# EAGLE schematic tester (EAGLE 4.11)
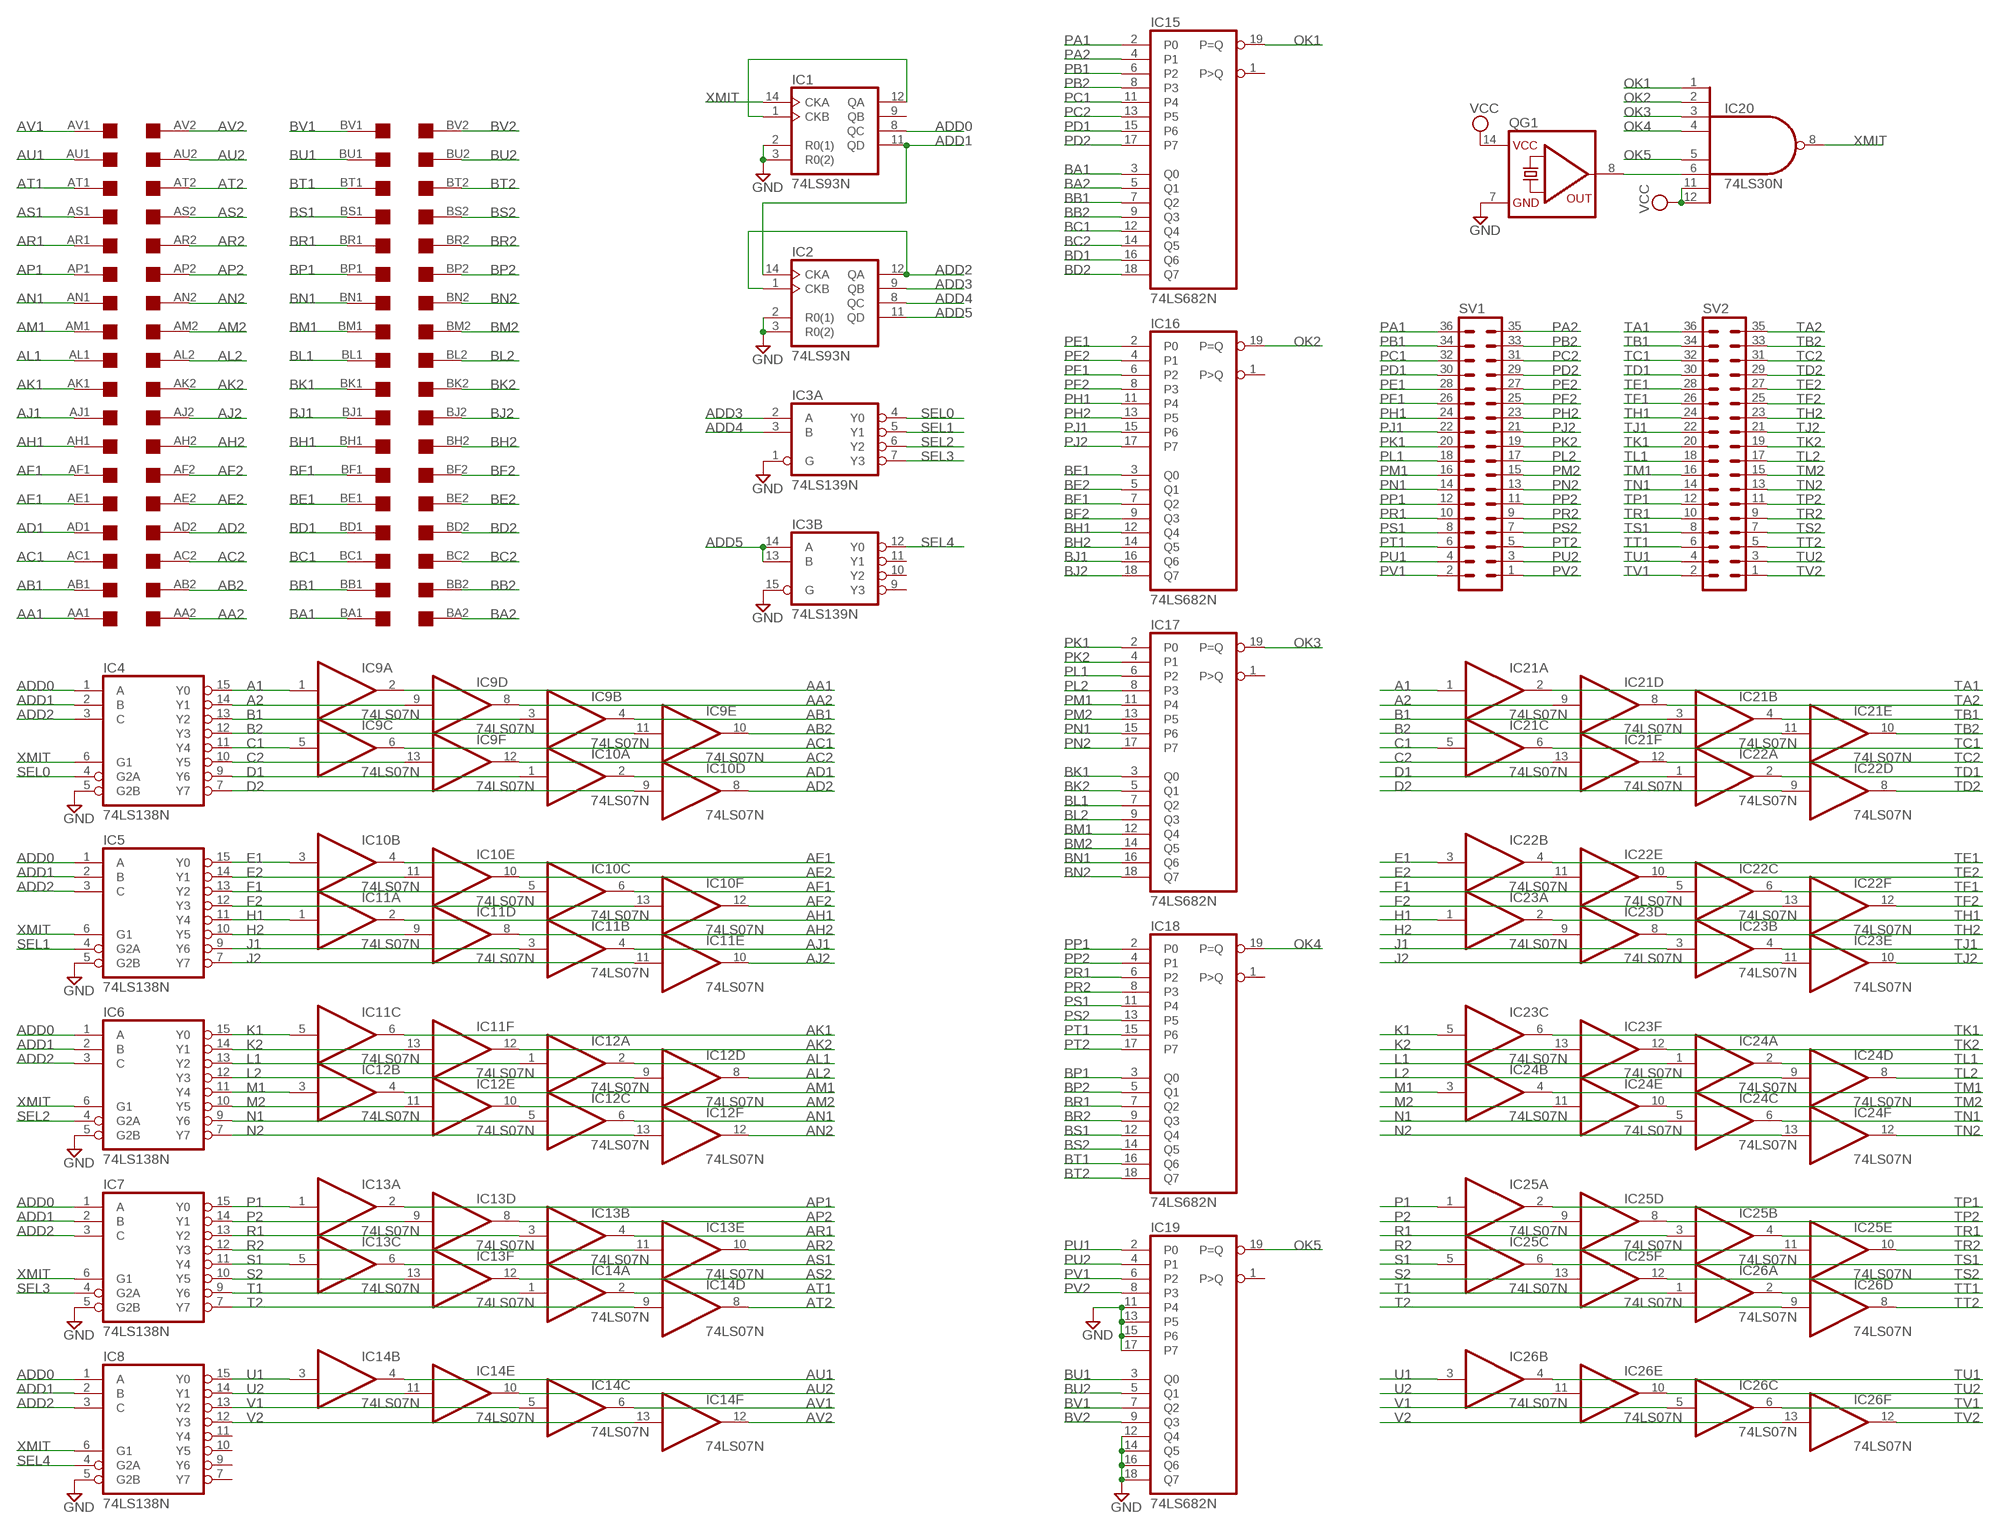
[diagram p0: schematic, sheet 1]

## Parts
IC1  74LS93N  [DIL14]
IC2  74LS93N  [DIL14]
IC3  74LS139N  [DIL16]
IC4  74LS138N  [DIL16]
IC5  74LS138N  [DIL16]
IC6  74LS138N  [DIL16]
IC7  74LS138N  [DIL16]
IC8  74LS138N  [DIL16]
IC9  74LS07N  [DIL14]
IC10  74LS07N  [DIL14]
IC11  74LS07N  [DIL14]
IC12  74LS07N  [DIL14]
IC13  74LS07N  [DIL14]
IC14  74LS07N  [DIL14]
IC15  74LS682N  [DIL20]
IC16  74LS682N  [DIL20]
IC17  74LS682N  [DIL20]
IC18  74LS682N  [DIL20]
IC19  74LS682N  [DIL20]
IC20  74LS30N  [DIL14]
IC21  74LS07N  [DIL14]
IC22  74LS07N  [DIL14]
IC23  74LS07N  [DIL14]
IC24  74LS07N  [DIL14]
IC25  74LS07N  [DIL14]
IC26  74LS07N  [DIL14]
QG1  QG5860  [DIL14S]
SV1  MA18-2  [MA18-2]
SV2  MA18-2  [MA18-2]
U$1  DOUBLEBOARD  [DOUBLE]

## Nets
A1: IC4.15(Y0) IC9.1(A:I) IC21.1(A:I)
A2: IC4.14(Y1) IC9.9(D:I) IC21.9(D:I)
AA1: IC9.2(A:O) U$1.AA1
AA2: IC9.8(D:O) U$1.AA2
AB1: IC9.4(B:O) U$1.AB1
AB2: IC9.10(E:O) U$1.AB2
AC1: IC9.6(C:O) U$1.AC1
AC2: IC9.12(F:O) U$1.AC2
AD1: IC10.2(A:O) U$1.AD1
AD2: IC10.8(D:O) U$1.AD2
ADD0: IC1.8(QC) IC4.1(A) IC5.1(A) IC6.1(A) IC7.1(A) IC8.1(A)
ADD1: IC1.11(QD) IC2.14(CKA) IC4.2(B) IC5.2(B) IC6.2(B) IC7.2(B) IC8.2(B)
ADD2: IC2.1(CKB) IC2.12(QA) IC4.3(C) IC5.3(C) IC6.3(C) IC7.3(C) IC8.3(C)
ADD3: IC2.9(QB) IC3.2(A:A)
ADD4: IC2.8(QC) IC3.3(A:B)
ADD5: IC2.11(QD) IC3.13(B:B) IC3.14(B:A)
AE1: IC10.4(B:O) U$1.AE1
AE2: IC10.10(E:O) U$1.AE2
AF1: IC10.6(C:O) U$1.AF1
AF2: IC10.12(F:O) U$1.AF2
AH1: IC11.2(A:O) U$1.AH1
AH2: IC11.8(D:O) U$1.AH2
AJ1: IC11.4(B:O) U$1.AJ1
AJ2: IC11.10(E:O) U$1.AJ2
AK1: IC11.6(C:O) U$1.AK1
AK2: IC11.12(F:O) U$1.AK2
AL1: IC12.2(A:O) U$1.AL1
AL2: IC12.8(D:O) U$1.AL2
AM1: IC12.4(B:O) U$1.AM1
AM2: IC12.10(E:O) U$1.AM2
AN1: IC12.6(C:O) U$1.AN1
AN2: IC12.12(F:O) U$1.AN2
AP1: IC13.2(A:O) U$1.AP1
AP2: IC13.8(D:O) U$1.AP2
AR1: IC13.4(B:O) U$1.AR1
AR2: IC13.10(E:O) U$1.AR2
AS1: IC13.6(C:O) U$1.AS1
AS2: IC13.12(F:O) U$1.AS2
AT1: IC14.2(A:O) U$1.AT1
AT2: IC14.8(D:O) U$1.AT2
AU1: IC14.4(B:O) U$1.AU1
AU2: IC14.10(E:O) U$1.AU2
AV1: IC14.6(C:O) U$1.AV1
AV2: IC14.12(F:O) U$1.AV2
B1: IC4.13(Y2) IC9.3(B:I) IC21.3(B:I)
B2: IC4.12(Y3) IC9.11(E:I) IC21.11(E:I)
BA1: IC15.3(Q0) U$1.BA1
BA2: IC15.5(Q1) U$1.BA2
BB1: IC15.7(Q2) U$1.BB1
BB2: IC15.9(Q3) U$1.BB2
BC1: IC15.12(Q4) U$1.BC1
BC2: IC15.14(Q5) U$1.BC2
BD1: IC15.16(Q6) U$1.BD1
BD2: IC15.18(Q7) U$1.BD2
BE1: IC16.3(Q0) U$1.BE1
BE2: IC16.5(Q1) U$1.BE2
BF1: IC16.7(Q2) U$1.BF1
BF2: IC16.9(Q3) U$1.BF2
BH1: IC16.12(Q4) U$1.BH1
BH2: IC16.14(Q5) U$1.BH2
BJ1: IC16.16(Q6) U$1.BJ1
BJ2: IC16.18(Q7) U$1.BJ2
BK1: IC17.3(Q0) U$1.BK1
BK2: IC17.5(Q1) U$1.BK2
BL1: IC17.7(Q2) U$1.BL1
BL2: IC17.9(Q3) U$1.BL2
BM1: IC17.12(Q4) U$1.BM1
BM2: IC17.14(Q5) U$1.BM2
BN1: IC17.16(Q6) U$1.BN1
BN2: IC17.18(Q7) U$1.BN2
BP1: IC18.3(Q0) U$1.BP1
BP2: IC18.5(Q1) U$1.BP2
BR1: IC18.7(Q2) U$1.BR1
BR2: IC18.9(Q3) U$1.BR2
BS1: IC18.12(Q4) U$1.BS1
BS2: IC18.14(Q5) U$1.BS2
BT1: IC18.16(Q6) U$1.BT1
BT2: IC18.18(Q7) U$1.BT2
BU1: IC19.3(Q0) U$1.BU1
BU2: IC19.5(Q1) U$1.BU2
BV1: IC19.7(Q2) U$1.BV1
BV2: IC19.9(Q3) U$1.BV2
C1: IC4.11(Y4) IC9.5(C:I) IC21.5(C:I)
C2: IC4.10(Y5) IC9.13(F:I) IC21.13(F:I)
CLK1: IC1.1(CKB) IC1.12(QA)
D1: IC4.9(Y6) IC10.1(A:I) IC22.1(A:I)
D2: IC4.7(Y7) IC10.9(D:I) IC22.9(D:I)
E1: IC5.15(Y0) IC10.3(B:I) IC22.3(B:I)
E2: IC5.14(Y1) IC10.11(E:I) IC22.11(E:I)
F1: IC5.13(Y2) IC10.5(C:I) IC22.5(C:I)
F2: IC5.12(Y3) IC10.13(F:I) IC22.13(F:I)
GND: IC1.2(R0(1)) IC1.3(R0(2)) IC2.2(R0(1)) IC2.3(R0(2)) IC3.1(A:G) IC3.15(B:G) IC4.5(G2B) IC5.5(G2B) IC6.5(G2B) IC7.5(G2B) IC8.5(G2B) IC19.11(P4) IC19.12(Q4) IC19.13(P5) IC19.14(Q5) IC19.15(P6) IC19.16(Q6) IC19.17(P7) IC19.18(Q7) QG1.7(GND)
H1: IC5.11(Y4) IC11.1(A:I) IC23.1(A:I)
H2: IC5.10(Y5) IC11.9(D:I) IC23.9(D:I)
J1: IC5.9(Y6) IC11.3(B:I) IC23.3(B:I)
J2: IC5.7(Y7) IC11.11(E:I) IC23.11(E:I)
K1: IC6.15(Y0) IC11.5(C:I) IC23.5(C:I)
K2: IC6.14(Y1) IC11.13(F:I) IC23.13(F:I)
L1: IC6.13(Y2) IC12.1(A:I) IC24.1(A:I)
L2: IC6.12(Y3) IC12.9(D:I) IC24.9(D:I)
M1: IC6.11(Y4) IC12.3(B:I) IC24.3(B:I)
M2: IC6.10(Y5) IC12.11(E:I) IC24.11(E:I)
N1: IC6.9(Y6) IC12.5(C:I) IC24.5(C:I)
N2: IC6.7(Y7) IC12.13(F:I) IC24.13(F:I)
N$1: IC20.6(I5) QG1.8(OUT)
OK1: IC15.19(P=Q) IC20.1(I0)
OK2: IC16.19(P=Q) IC20.2(I1)
OK3: IC17.19(P=Q) IC20.3(I2)
OK4: IC18.19(P=Q) IC20.4(I3)
OK5: IC19.19(P=Q) IC20.5(I4)
P1: IC7.15(Y0) IC13.1(A:I) IC25.1(A:I)
P2: IC7.14(Y1) IC13.9(D:I) IC25.9(D:I)
PA1: IC15.2(P0) SV1.36
PA2: IC15.4(P1) SV1.35
PB1: IC15.6(P2) SV1.34
PB2: IC15.8(P3) SV1.33
PC1: IC15.11(P4) SV1.32
PC2: IC15.13(P5) SV1.31
PD1: IC15.15(P6) SV1.30
PD2: IC15.17(P7) SV1.29
PE1: IC16.2(P0) SV1.28
PE2: IC16.4(P1) SV1.27
PF1: IC16.6(P2) SV1.26
PF2: IC16.8(P3) SV1.25
PH1: IC16.11(P4) SV1.24
PH2: IC16.13(P5) SV1.23
PJ1: IC16.15(P6) SV1.22
PJ2: IC16.17(P7) SV1.21
PK1: IC17.2(P0) SV1.20
PK2: IC17.4(P1) SV1.19
PL1: IC17.6(P2) SV1.18
PL2: IC17.8(P3) SV1.17
PM1: IC17.11(P4) SV1.16
PM2: IC17.13(P5) SV1.15
PN1: IC17.15(P6) SV1.14
PN2: IC17.17(P7) SV1.13
PP1: IC18.2(P0) SV1.12
PP2: IC18.4(P1) SV1.11
PR1: IC18.6(P2) SV1.10
PR2: IC18.8(P3) SV1.9
PS1: IC18.11(P4) SV1.8
PS2: IC18.13(P5) SV1.7
PT1: IC18.15(P6) SV1.6
PT2: IC18.17(P7) SV1.5
PU1: IC19.2(P0) SV1.4
PU2: IC19.4(P1) SV1.3
PV1: IC19.6(P2) SV1.2
PV2: IC19.8(P3) SV1.1
R1: IC7.13(Y2) IC13.3(B:I) IC25.3(B:I)
R2: IC7.12(Y3) IC13.11(E:I) IC25.11(E:I)
S1: IC7.11(Y4) IC13.5(C:I) IC25.5(C:I)
S2: IC7.10(Y5) IC13.13(F:I) IC25.13(F:I)
SEL0: IC3.4(A:Y0) IC4.4(G2A)
SEL1: IC3.5(A:Y1) IC5.4(G2A)
SEL2: IC3.6(A:Y2) IC6.4(G2A)
SEL3: IC3.7(A:Y3) IC7.4(G2A)
SEL4: IC3.12(B:Y0) IC8.4(G2A)
T1: IC7.9(Y6) IC14.1(A:I) IC26.1(A:I)
T2: IC7.7(Y7) IC14.9(D:I) IC26.9(D:I)
TA1: IC21.2(A:O) SV2.36
TA2: IC21.8(D:O) SV2.35
TB1: IC21.4(B:O) SV2.34
TB2: IC21.10(E:O) SV2.33
TC1: IC21.6(C:O) SV2.32
TC2: IC21.12(F:O) SV2.31
TD1: IC22.2(A:O) SV2.30
TD2: IC22.8(D:O) SV2.29
TE1: IC22.4(B:O) SV2.28
TE2: IC22.10(E:O) SV2.27
TF1: IC22.6(C:O) SV2.26
TF2: IC22.12(F:O) SV2.25
TH1: IC23.2(A:O) SV2.24
TH2: IC23.8(D:O) SV2.23
TJ1: IC23.4(B:O) SV2.22
TJ2: IC23.10(E:O) SV2.21
TK1: IC23.6(C:O) SV2.20
TK2: IC23.12(F:O) SV2.19
TL1: IC24.2(A:O) SV2.18
TL2: IC24.8(D:O) SV2.17
TM1: IC24.4(B:O) SV2.16
TM2: IC24.10(E:O) SV2.15
TN1: IC24.6(C:O) SV2.14
TN2: IC24.12(F:O) SV2.13
TP1: IC25.2(A:O) SV2.12
TP2: IC25.8(D:O) SV2.11
TR1: IC25.4(B:O) SV2.10
TR2: IC25.10(E:O) SV2.9
TS1: IC25.6(C:O) SV2.8
TS2: IC25.12(F:O) SV2.7
TT1: IC26.2(A:O) SV2.6
TT2: IC26.8(D:O) SV2.5
TU1: IC26.4(B:O) SV2.4
TU2: IC26.10(E:O) SV2.3
TV1: IC26.6(C:O) SV2.2
TV2: IC26.12(F:O) SV2.1
U1: IC8.15(Y0) IC14.3(B:I) IC26.3(B:I)
U2: IC8.14(Y1) IC14.11(E:I) IC26.11(E:I)
V1: IC8.13(Y2) IC14.5(C:I) IC26.5(C:I)
V2: IC8.12(Y3) IC14.13(F:I) IC26.13(F:I)
VCC: IC20.11(I6) IC20.12(I7) QG1.14(VCC)
XMIT: IC1.14(CKA) IC4.6(G1) IC5.6(G1) IC6.6(G1) IC7.6(G1) IC8.6(G1) IC20.8(O)
Unconnected: IC1.9(QB) IC3.9(B:Y3) IC3.10(B:Y2) IC3.11(B:Y1) IC8.7(Y7) IC8.9(Y6) IC8.10(Y5) IC8.11(Y4) IC15.1(P>Q) IC16.1(P>Q) IC17.1(P>Q) IC18.1(P>Q) IC19.1(P>Q)

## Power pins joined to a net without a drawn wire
GND: IC1.10(GND) IC2.10(GND) IC3.8(P:GND) IC4.8(GND) IC5.8(GND) IC6.8(GND) IC7.8(GND) IC8.8(GND) IC9.7(P:GND) IC10.7(P:GND) IC11.7(P:GND) IC12.7(P:GND) IC13.7(P:GND) IC14.7(P:GND) IC15.10(GND) IC16.10(GND) IC17.10(GND) IC18.10(GND) IC19.10(GND) IC20.7(GND) IC21.7(P:GND) IC22.7(P:GND) IC23.7(P:GND) IC24.7(P:GND) IC25.7(P:GND) IC26.7(P:GND)
VCC: IC1.5(VCC) IC2.5(VCC) IC3.16(P:VCC) IC4.16(VCC) IC5.16(VCC) IC6.16(VCC) IC7.16(VCC) IC8.16(VCC) IC9.14(P:VCC) IC10.14(P:VCC) IC11.14(P:VCC) IC12.14(P:VCC) IC13.14(P:VCC) IC14.14(P:VCC) IC15.20(VCC) IC16.20(VCC) IC17.20(VCC) IC18.20(VCC) IC19.20(VCC) IC20.14(VCC) IC21.14(P:VCC) IC22.14(P:VCC) IC23.14(P:VCC) IC24.14(P:VCC) IC25.14(P:VCC) IC26.14(P:VCC)

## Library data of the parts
IC1 IC2 = 74xx-us:74*93: Decade, divide by twelve and binary COUNTER
IC3 = 74xx-us:74*139: Dual 2-line to 4-line DECODER/DEMULTIPLEXER
IC4-IC8 = 74xx-us:74*138: 3-line to 8-line DECODER/DEMULTIPLEXER
IC9-IC14 IC21-IC26 = 74xx-us:74*07: Hex BUFFER, open collector high-voltage output
IC15-IC19 = 74xx-eu:74*682: 8-bit MAGNITUDE/IDENTITY COMPARATOR, totem pole
IC20 = 74xx-us:74*30: 8-input NAND gate
QG1 = crystal:QG5860: CRYSTAL RESONATOR
SV1 SV2 = con-lstb:MA18-2: PIN HEADER
U$1 = dec-con:DOUBLE: Double-Height DEC board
